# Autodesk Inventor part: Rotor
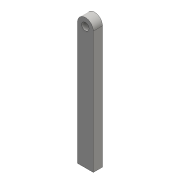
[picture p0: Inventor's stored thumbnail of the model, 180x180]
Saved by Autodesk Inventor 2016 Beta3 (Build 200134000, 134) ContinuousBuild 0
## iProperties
Created: 2016-03
Part Number: Rotor
Material: Generic
Document SubType Name: Modeling
Designer: Gaurav
Density: 1 g/cm^3
Appearance: Default
Author: Gaurav
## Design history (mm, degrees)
sketch "Sketch1"
  geometry: L1 (2.143, 0)-(2.143, -33.249); L2 (2.143, -33.249)-(-2.143, -33.249); L3 (-2.143, -33.249)-(-2.143, 0); C1 r 1 at (0, 0); A1 r 2.143 centre (0, 0) between (2.143, 0) and (-2.143, 0); 1 further point
  constraints: 6 end point, 2 centre point, 2 coincident, 2 point on circle, 1 perpendicular, 1 tangent, 1 vertical
  dimensions: "d0" = 2 diameter of C1
extrude "Extrusion1" new body sketch "Sketch1" distance "d1" = 2.5; taper "d2" = 0 deg
body "Solid1"
